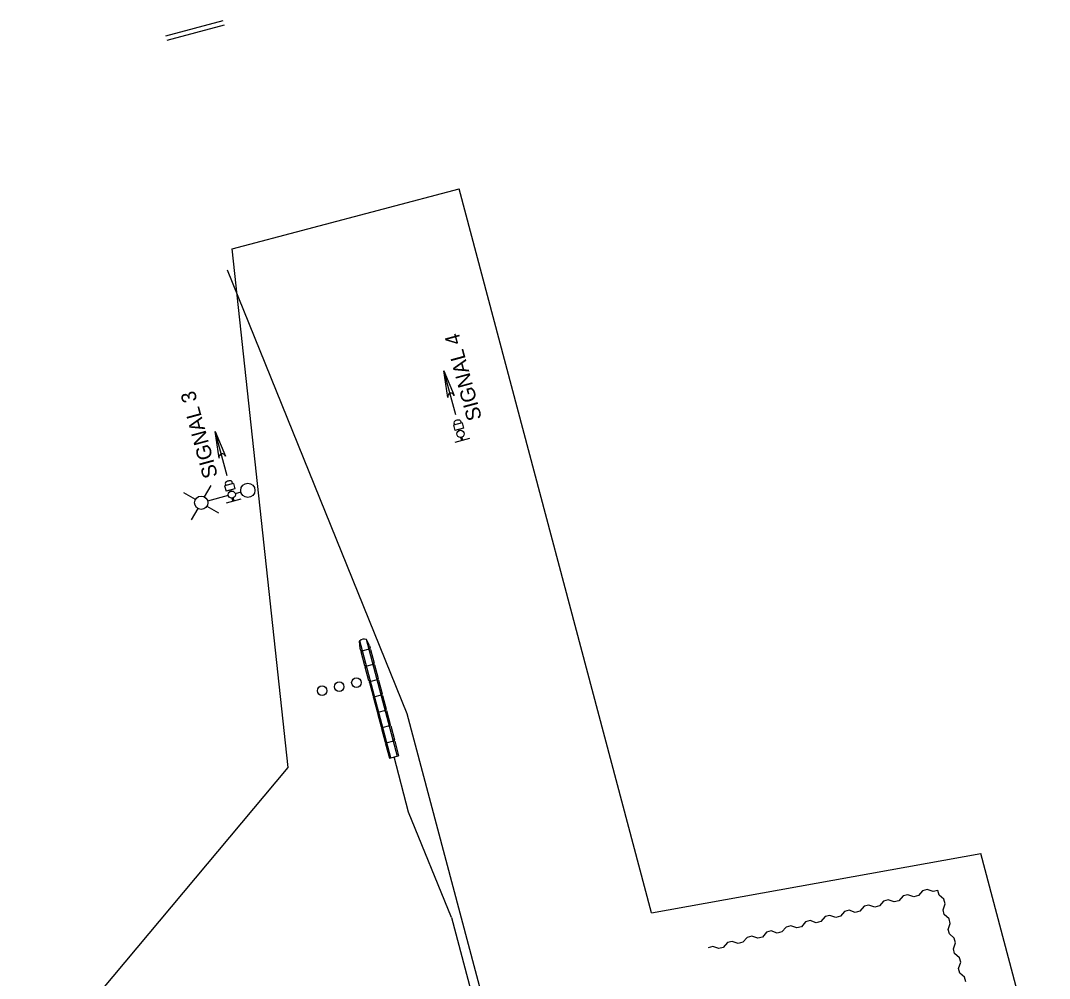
# Model space of a CAD drawing. Extents: x 2047712 to 2051245, y 280285 to 283042.
# Drawn here: x 2047720 to 2047936.7, y 281989.1 to 282190.9 of the extents above; entities that cross this region are included whole.
import ezdxf

# ---------------------------------------------------------------- set-up
doc = ezdxf.new("R2010")
doc.units = 0
for name, color, linetype in [('RW_X_CL_100_Distances', 7, 'Continuous'), ('RW_X_CL_100_Stations', 7, 'Continuous'), ('RW_X_Esmt_SH', 7, 'Continuous'), ('SC_Scratch1', 7, 'Continuous'), ('SV_Control_Point', 7, 'Continuous')]:
    doc.layers.add(name, color=color, linetype=linetype)

msp = doc.modelspace()

# ---------------------------------------------------------------- linework, layer by layer
at = {"layer": 'RW_X_CL_100_Distances'}
for p, q in [((2047763.52, 282138.4), (2047801.42, 282044.99)), ((2047791.58, 282058.67), (2047791.44, 282060.19)), ((2047798.05, 282035.63), (2047791.51, 282060.26)), ((2047791.69, 282058.25), (2047791.58, 282058.67)), ((2047791.9, 282058.13), (2047793.51, 282058.56)), ((2047792.79, 282060.6), (2047799.33, 282035.97)), ((2047793.51, 282059.19), (2047792.89, 282060.57)), ((2047793.51, 282059.19), (2047793.63, 282058.77)), ((2047793.51, 282058.56), (2047793.63, 282058.77)), ((2047793.71, 282058.44), (2047793.51, 282058.56)), ((2047791.9, 282058.13), (2047791.69, 282058.25)), ((2047791.78, 282057.93), (2047791.9, 282058.13)), ((2047792.55, 282055.03), (2047791.78, 282057.93)), ((2047793.71, 282058.44), (2047794.48, 282055.54)), ((2047792.75, 282054.91), (2047792.55, 282055.03)), ((2047792.63, 282054.71), (2047792.75, 282054.91)), ((2047793.4, 282051.81), (2047792.63, 282054.71)), ((2047792.75, 282054.91), (2047794.36, 282055.34)), ((2047794.36, 282055.34), (2047794.48, 282055.54)), ((2047794.57, 282055.22), (2047794.36, 282055.34)), ((2047794.57, 282055.22), (2047795.34, 282052.32)), ((2047793.61, 282051.69), (2047795.22, 282052.12)), ((2047795.22, 282052.12), (2047795.34, 282052.32)), ((2047795.42, 282052), (2047795.22, 282052.12)), ((2047793.61, 282051.69), (2047793.4, 282051.81)), ((2047793.49, 282051.49), (2047793.61, 282051.69)), ((2047793.49, 282051.49), (2047794.26, 282048.59)), ((2047795.42, 282052), (2047796.19, 282049.1)), ((2047794.46, 282048.47), (2047794.26, 282048.59)), ((2047794.34, 282048.27), (2047794.46, 282048.47)), ((2047794.34, 282048.27), (2047795.11, 282045.37)), ((2047794.46, 282048.47), (2047796.07, 282048.9)), ((2047796.07, 282048.9), (2047796.19, 282049.1)), ((2047796.28, 282048.78), (2047796.07, 282048.9)), ((2047796.28, 282048.78), (2047797.05, 282045.88)), ((2047795.32, 282045.25), (2047796.93, 282045.68)), ((2047796.93, 282045.68), (2047797.05, 282045.88)), ((2047797.13, 282045.56), (2047796.93, 282045.68)), ((2047797.13, 282045.56), (2047797.9, 282042.66)), ((2047795.32, 282045.25), (2047795.11, 282045.37)), ((2047795.2, 282045.04), (2047795.32, 282045.25)), ((2047795.2, 282045.04), (2047795.97, 282042.14)), ((2047801.42, 282044.99), (2047860.7, 281821.73)), ((2047796.17, 282042.03), (2047795.97, 282042.14)), ((2047796.06, 282041.82), (2047796.17, 282042.03)), ((2047796.06, 282041.82), (2047796.83, 282038.92)), ((2047796.17, 282042.03), (2047797.78, 282042.45)), ((2047797.78, 282042.45), (2047797.9, 282042.66)), ((2047797.99, 282042.34), (2047797.78, 282042.45)), ((2047797.99, 282042.34), (2047798.76, 282039.44)), ((2047797.03, 282038.8), (2047798.64, 282039.23)), ((2047798.64, 282039.23), (2047798.76, 282039.44)), ((2047798.84, 282039.11), (2047798.64, 282039.23)), ((2047798.84, 282039.11), (2047799.66, 282036.05)), ((2047797.03, 282038.8), (2047796.83, 282038.92)), ((2047796.91, 282038.6), (2047797.03, 282038.8)), ((2047796.91, 282038.6), (2047797.72, 282035.54)), ((2047797.72, 282035.54), (2047799.66, 282036.05)), ((2047801.77, 282024.2), (2047798.69, 282035.8)), ((2047810.78, 282001.95), (2047801.77, 282024.2)), ((2047810.78, 282001.95), (2047847.73, 281862.78))]:
    msp.add_line(p, q, dxfattribs=at)
for centre in [(2047790.76, 282051.46), (2047783.54, 282049.77), (2047787.15, 282050.61)]:
    msp.add_circle(centre, 1, dxfattribs=at)
msp.add_arc((2047792.45, 282059.31), 1.34, 70.6941, 139.0454, dxfattribs=at)
at = {"layer": 'RW_X_CL_100_Stations'}
for p, q in [((2047811.74, 282107.85), (2047809.21, 282117.17)), ((2047810.01, 282111.56), (2047809.21, 282117.17)), ((2047809.21, 282117.17), (2047811.36, 282111.93)), ((2047812.68, 282106.6), (2047812.81, 282106.13)), ((2047812.68, 282106.6), (2047812.81, 282106.13)), ((2047763.57, 282095.06), (2047761.03, 282104.38)), ((2047761.83, 282098.77), (2047761.03, 282104.38)), ((2047761.03, 282104.38), (2047763.19, 282099.14)), ((2047813.05, 282106.19), (2047811.18, 282105.68)), ((2047811.18, 282105.68), (2047811.48, 282104.58)), ((2047811.29, 282106.22), (2047811.42, 282105.75)), ((2047811.29, 282106.22), (2047811.42, 282105.75)), ((2047813.35, 282105.09), (2047811.48, 282104.58)), ((2047812.37, 282104.54), (2047812.3, 282104.8)), ((2047812.37, 282104.54), (2047812.3, 282104.8)), ((2047812.6, 282104.61), (2047812.53, 282104.86)), ((2047812.6, 282104.61), (2047812.53, 282104.86)), ((2047813.05, 282106.19), (2047813.35, 282105.09)), ((2047814.62, 282102.92), (2047811.5, 282102.07)), ((2047812.94, 282102.47), (2047812.77, 282103.1)), ((2047812.94, 282102.47), (2047812.77, 282103.1)), ((2047813.17, 282102.53), (2047813, 282103.17)), ((2047813.17, 282102.53), (2047813, 282103.17)), ((2047764.87, 282093.41), (2047763, 282092.89)), ((2047763.11, 282093.43), (2047763.24, 282092.97)), ((2047764.5, 282093.81), (2047764.63, 282093.35)), ((2047764.87, 282093.41), (2047765.17, 282092.3)), ((2047756.87, 282090.07), (2047754.44, 282091.47)), ((2047758.78, 282090.57), (2047760.19, 282093)), ((2047763, 282092.89), (2047763.3, 282091.79)), ((2047765.17, 282092.3), (2047763.3, 282091.79)), ((2047764.19, 282091.76), (2047764.12, 282092.01)), ((2047764.19, 282091.76), (2047764.12, 282092.01)), ((2047764.42, 282091.82), (2047764.35, 282092.08)), ((2047764.42, 282091.82), (2047764.35, 282092.08)), ((2047766.45, 282091.59), (2047765.23, 282091.27)), ((2047763.77, 282090.87), (2047759.43, 282089.72)), ((2047766.44, 282090.14), (2047763.32, 282089.28)), ((2047764.76, 282089.68), (2047764.59, 282090.31)), ((2047765, 282089.74), (2047764.82, 282090.38)), ((2047757.37, 282088.15), (2047755.97, 282085.73)), ((2047759.29, 282088.66), (2047761.71, 282087.25))]:
    msp.add_line(p, q, dxfattribs=at)
for centre, radius in [((2047812.69, 282103.86), 0.757), ((2047767.9, 282091.97), 1.5), ((2047764.51, 282091.07), 0.757), ((2047758.08, 282089.36), 1.4)]:
    msp.add_circle(centre, radius, dxfattribs=at)
for centre in [(2047810.69, 282111.74), (2047762.51, 282098.95)]:
    msp.add_arc(centre, 0.703, 15.2079, 195.2079, dxfattribs=at)
for centre in [(2047811.99, 282106.41), (2047811.99, 282106.41), (2047763.81, 282093.62)]:
    msp.add_ellipse(centre, major_axis=(0.695, 0.19), ratio=0.45371, start_param=0, end_param=3.141593, dxfattribs=at)
at = {"layer": 'RW_X_Esmt_SH'}
for p, q in [((2047906.89, 282006.78), (2047905.92, 282006.52)), ((2047908.17, 282006.34), (2047906.89, 282006.78)), ((2047909.13, 282006.6), (2047908.17, 282006.34)), ((2047910.03, 282007.61), (2047909.13, 282006.6)), ((2047910.99, 282007.87), (2047910.03, 282007.61)), ((2047912.27, 282007.43), (2047910.99, 282007.87)), ((2047913.24, 282007.69), (2047912.27, 282007.43)), ((2047913.5, 282006.72), (2047913.24, 282007.69)), ((2047914.51, 282005.83), (2047913.5, 282006.72)), ((2047898.67, 282004.6), (2047897.7, 282004.34)), ((2047899.95, 282004.16), (2047898.67, 282004.6)), ((2047900.92, 282004.42), (2047899.95, 282004.16)), ((2047901.81, 282005.43), (2047900.92, 282004.42)), ((2047902.78, 282005.69), (2047901.81, 282005.43)), ((2047904.06, 282005.25), (2047902.78, 282005.69)), ((2047905.02, 282005.51), (2047904.06, 282005.25)), ((2047905.92, 282006.52), (2047905.02, 282005.51)), ((2047914.33, 282003.58), (2047914.77, 282004.86)), ((2047914.77, 282004.86), (2047914.51, 282005.83)), ((2047890.45, 282002.42), (2047889.49, 282002.16)), ((2047891.73, 282001.98), (2047890.45, 282002.42)), ((2047892.7, 282002.24), (2047891.73, 282001.98)), ((2047893.6, 282003.25), (2047892.7, 282002.24)), ((2047894.56, 282003.51), (2047893.6, 282003.25)), ((2047895.84, 282003.07), (2047894.56, 282003.51)), ((2047896.81, 282003.33), (2047895.84, 282003.07)), ((2047897.7, 282004.34), (2047896.81, 282003.33)), ((2047914.59, 282002.62), (2047914.33, 282003.58)), ((2047915.6, 282001.72), (2047914.59, 282002.62)), ((2047882.24, 282000.23), (2047881.27, 281999.98)), ((2047883.52, 281999.8), (2047882.24, 282000.23)), ((2047884.49, 282000.05), (2047883.52, 281999.8)), ((2047885.38, 282001.07), (2047884.49, 282000.05)), ((2047886.35, 282001.33), (2047885.38, 282001.07)), ((2047887.63, 282000.89), (2047886.35, 282001.33)), ((2047888.59, 282001.15), (2047887.63, 282000.89)), ((2047889.49, 282002.16), (2047888.59, 282001.15)), ((2047915.42, 281999.47), (2047915.86, 282000.75)), ((2047915.86, 282000.75), (2047915.6, 282001.72)), ((2047874.02, 281998.05), (2047873.06, 281997.8)), ((2047875.3, 281997.62), (2047874.02, 281998.05)), ((2047877.16, 281998.89), (2047876.27, 281997.87)), ((2047878.13, 281999.14), (2047877.16, 281998.89)), ((2047879.41, 281998.71), (2047878.13, 281999.14)), ((2047880.38, 281998.96), (2047879.41, 281998.71)), ((2047881.27, 281999.98), (2047880.38, 281998.96)), ((2047915.68, 281998.51), (2047915.42, 281999.47)), ((2047916.69, 281997.61), (2047915.68, 281998.51)), ((2047865.81, 281995.87), (2047864.84, 281995.62)), ((2047867.09, 281995.44), (2047865.81, 281995.87)), ((2047868.95, 281996.71), (2047868.05, 281995.69)), ((2047869.92, 281996.96), (2047868.95, 281996.71)), ((2047871.2, 281996.53), (2047869.92, 281996.96)), ((2047872.16, 281996.78), (2047871.2, 281996.53)), ((2047873.06, 281997.8), (2047872.16, 281996.78)), ((2047876.27, 281997.87), (2047875.3, 281997.62)), ((2047916.51, 281995.37), (2047916.95, 281996.65)), ((2047916.95, 281996.65), (2047916.69, 281997.61)), ((2047868.05, 281995.69), (2047867.09, 281995.44)), ((2047916.77, 281994.4), (2047916.51, 281995.37)), ((2047917.78, 281993.51), (2047916.77, 281994.4)), ((2047917.6, 281991.26), (2047918.04, 281992.54)), ((2047918.04, 281992.54), (2047917.78, 281993.51)), ((2047917.86, 281990.29), (2047917.6, 281991.26)), ((2047918.87, 281989.4), (2047917.86, 281990.29)), ((2047919.13, 281988.43), (2047918.87, 281989.4))]:
    msp.add_line(p, q, dxfattribs=at)
at = {"layer": 'SC_Scratch1'}
for p, q in [((2047750.59, 282187.73), (2047762.67, 282190.94)), ((2047762.93, 282189.97), (2047750.85, 282186.76))]:
    msp.add_line(p, q, dxfattribs=at)
at = {"layer": 'SV_Control_Point'}
for p, q in [((2047764.62, 282142.83), (2047812.43, 282155.52)), ((2047852.93, 282002.98), (2047812.43, 282155.52)), ((2047852.93, 282002.98), (2047922.3, 282015.45)), ((2047936.73, 281961.09), (2047922.3, 282015.45))]:
    msp.add_line(p, q, dxfattribs=at)
msp.add_lwpolyline([(2047720.03, 281966.22), (2047776.38, 282033.57), (2047764.62, 282142.83)], dxfattribs=at)

# ---------------------------------------------------------------- texts
at = {"layer": 'RW_X_CL_100_Stations'}
for s, p in [('SIGNAL 4', (2047817.23, 282107.13)), ('SIGNAL 3', (2047761.61, 282095))]:
    msp.add_text(s, height=3.125, rotation=105.2079, dxfattribs=at).set_placement(p)

doc.saveas('drawing.dxf')
